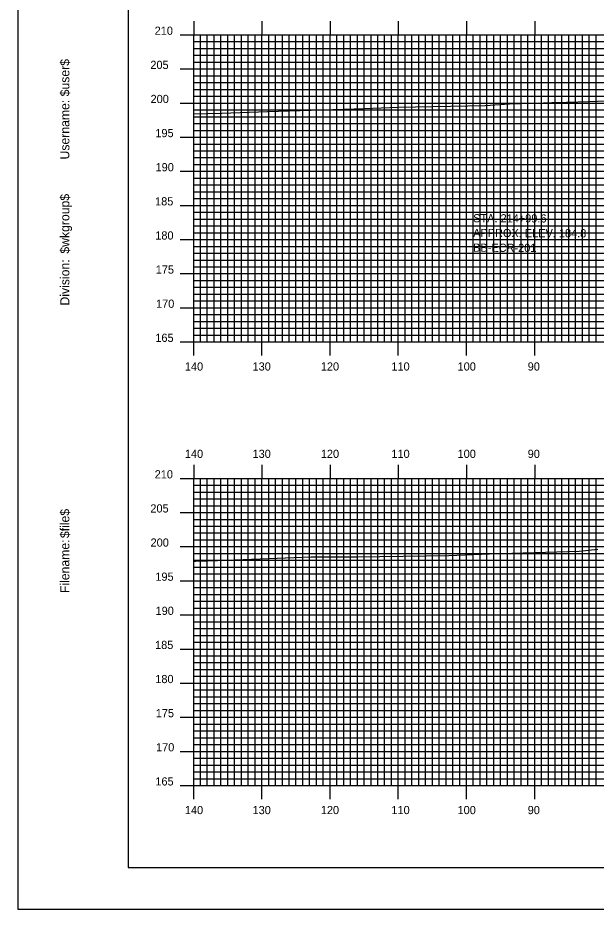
# Model space of a CAD drawing. Extents: x 1796027 to 1796370, y 442591 to 442811.
# Drawn here: x 1796026.6 to 1796111.4, y 442590.5 to 442721.2 of the extents above; entities that cross this region are included whole.
import ezdxf

# ---------------------------------------------------------------- set-up
doc = ezdxf.new("R2010")
doc.units = 0
for name, color, linetype in [('BORDER', 7, 'Continuous'), ('BORING - REFUSAL', 7, 'Continuous'), ('D_Roadway_Centerline', 7, 'Continuous'), ('H_V ANNOTATION', 7, 'Continuous'), ('MAJOR', 7, 'Continuous'), ('MINOR', 7, 'Continuous'), ('PLOT BOUNDARY', 7, 'Continuous'), ('S_Roadway_Centerline', 7, 'Continuous')]:
    doc.layers.add(name, color=color, linetype=linetype)

msp = doc.modelspace()

# ---------------------------------------------------------------- linework, layer by layer
at = {"layer": 'BORDER'}
msp.add_lwpolyline([(1796042.79, 442596.67), (1796362.79, 442596.67), (1796362.79, 442806.67), (1796042.79, 442806.67)], close=True, dxfattribs=at)
at = {"layer": 'D_Roadway_Centerline'}
msp.add_lwpolyline([(1796104.9, 442708.75), (1796105.52, 442708.73)], dxfattribs=at)
at = {"layer": 'MAJOR'}
for p, q in [((1796052.39, 442720.67), (1796052.39, 442718.67)), ((1796062.39, 442720.67), (1796062.39, 442718.67)), ((1796072.39, 442720.67), (1796072.39, 442718.67)), ((1796082.39, 442720.67), (1796082.39, 442718.67)), ((1796092.39, 442720.67), (1796092.39, 442718.67)), ((1796102.39, 442720.67), (1796102.39, 442718.67)), ((1796050.39, 442718.67), (1796052.39, 442718.67)), ((1796052.39, 442718.67), (1796332.39, 442718.67)), ((1796052.39, 442673.67), (1796052.39, 442718.67)), ((1796052.39, 442673.67), (1796052.39, 442718.67)), ((1796052.39, 442718.67), (1796332.39, 442718.67)), ((1796062.39, 442673.67), (1796062.39, 442718.67)), ((1796072.39, 442673.67), (1796072.39, 442718.67)), ((1796082.39, 442673.67), (1796082.39, 442718.67)), ((1796092.39, 442673.67), (1796092.39, 442718.67)), ((1796102.39, 442673.67), (1796102.39, 442718.67)), ((1796050.39, 442713.67), (1796052.39, 442713.67)), ((1796052.39, 442713.67), (1796332.39, 442713.67)), ((1796050.39, 442708.67), (1796052.39, 442708.67)), ((1796052.39, 442708.67), (1796332.39, 442708.67)), ((1796050.39, 442703.67), (1796052.39, 442703.67)), ((1796052.39, 442703.67), (1796332.39, 442703.67)), ((1796050.39, 442698.67), (1796052.39, 442698.67)), ((1796052.39, 442698.67), (1796332.39, 442698.67)), ((1796050.39, 442693.67), (1796052.39, 442693.67)), ((1796052.39, 442693.67), (1796332.39, 442693.67)), ((1796050.39, 442688.67), (1796052.39, 442688.67)), ((1796052.39, 442688.67), (1796332.39, 442688.67)), ((1796050.39, 442683.67), (1796052.39, 442683.67)), ((1796052.39, 442683.67), (1796332.39, 442683.67)), ((1796050.39, 442678.67), (1796052.39, 442678.67)), ((1796052.39, 442678.67), (1796332.39, 442678.67)), ((1796050.39, 442673.67), (1796052.39, 442673.67)), ((1796052.39, 442673.67), (1796332.39, 442673.67)), ((1796052.39, 442673.67), (1796332.39, 442673.67)), ((1796052.39, 442671.66), (1796052.39, 442673.67)), ((1796062.39, 442671.66), (1796062.39, 442673.67)), ((1796072.39, 442671.66), (1796072.39, 442673.67)), ((1796082.39, 442671.66), (1796082.39, 442673.67)), ((1796092.39, 442671.66), (1796092.39, 442673.67)), ((1796102.39, 442671.66), (1796102.39, 442673.67)), ((1796052.39, 442655.67), (1796052.39, 442653.67)), ((1796062.39, 442655.67), (1796062.39, 442653.67)), ((1796072.39, 442655.67), (1796072.39, 442653.67)), ((1796082.39, 442655.67), (1796082.39, 442653.67)), ((1796092.39, 442655.67), (1796092.39, 442653.67)), ((1796102.39, 442655.67), (1796102.39, 442653.67)), ((1796050.39, 442653.67), (1796052.39, 442653.67)), ((1796052.39, 442653.67), (1796332.39, 442653.67)), ((1796052.39, 442608.67), (1796052.39, 442653.67)), ((1796052.39, 442608.67), (1796052.39, 442653.67)), ((1796052.39, 442653.67), (1796332.39, 442653.67)), ((1796062.39, 442608.67), (1796062.39, 442653.67)), ((1796072.39, 442608.67), (1796072.39, 442653.67)), ((1796082.39, 442608.67), (1796082.39, 442653.67)), ((1796092.39, 442608.67), (1796092.39, 442653.67)), ((1796102.39, 442608.67), (1796102.39, 442653.67)), ((1796050.39, 442648.67), (1796052.39, 442648.67)), ((1796052.39, 442648.67), (1796332.39, 442648.67)), ((1796050.39, 442643.67), (1796052.39, 442643.67)), ((1796052.39, 442643.67), (1796332.39, 442643.67)), ((1796050.39, 442638.67), (1796052.39, 442638.67)), ((1796052.39, 442638.67), (1796332.39, 442638.67)), ((1796050.39, 442633.67), (1796052.39, 442633.67)), ((1796052.39, 442633.67), (1796332.39, 442633.67)), ((1796050.39, 442628.67), (1796052.39, 442628.67)), ((1796052.39, 442628.67), (1796332.39, 442628.67)), ((1796050.39, 442623.67), (1796052.39, 442623.67)), ((1796052.39, 442623.67), (1796332.39, 442623.67)), ((1796050.39, 442618.67), (1796052.39, 442618.67)), ((1796052.39, 442618.67), (1796332.39, 442618.67)), ((1796050.39, 442613.67), (1796052.39, 442613.67)), ((1796052.39, 442613.67), (1796332.39, 442613.67)), ((1796050.39, 442608.67), (1796052.39, 442608.67)), ((1796052.39, 442608.67), (1796332.39, 442608.67)), ((1796052.39, 442608.67), (1796332.39, 442608.67)), ((1796052.39, 442606.66), (1796052.39, 442608.67)), ((1796062.39, 442606.66), (1796062.39, 442608.67)), ((1796072.39, 442606.66), (1796072.39, 442608.67)), ((1796082.39, 442606.66), (1796082.39, 442608.67)), ((1796092.39, 442606.66), (1796092.39, 442608.67)), ((1796102.39, 442606.66), (1796102.39, 442608.67))]:
    msp.add_line(p, q, dxfattribs=at)
at = {"layer": 'MINOR'}
for p, q in [((1796053.39, 442673.67), (1796053.39, 442718.67)), ((1796054.39, 442673.67), (1796054.39, 442718.67)), ((1796055.39, 442673.67), (1796055.39, 442718.67)), ((1796056.39, 442673.67), (1796056.39, 442718.67)), ((1796057.39, 442673.67), (1796057.39, 442718.67)), ((1796058.39, 442673.67), (1796058.39, 442718.67)), ((1796059.39, 442673.67), (1796059.39, 442718.67)), ((1796060.39, 442673.67), (1796060.39, 442718.67)), ((1796061.39, 442673.67), (1796061.39, 442718.67)), ((1796063.39, 442673.67), (1796063.39, 442718.67)), ((1796064.39, 442673.67), (1796064.39, 442718.67)), ((1796065.39, 442673.67), (1796065.39, 442718.67)), ((1796066.39, 442673.67), (1796066.39, 442718.67)), ((1796067.39, 442673.67), (1796067.39, 442718.67)), ((1796068.39, 442673.67), (1796068.39, 442718.67)), ((1796069.39, 442673.67), (1796069.39, 442718.67)), ((1796070.39, 442673.67), (1796070.39, 442718.67)), ((1796071.39, 442673.67), (1796071.39, 442718.67)), ((1796073.39, 442673.67), (1796073.39, 442718.67)), ((1796074.39, 442673.67), (1796074.39, 442718.67)), ((1796075.39, 442673.67), (1796075.39, 442718.67)), ((1796076.39, 442673.67), (1796076.39, 442718.67)), ((1796077.39, 442673.67), (1796077.39, 442718.67)), ((1796078.39, 442673.67), (1796078.39, 442718.67)), ((1796079.39, 442673.67), (1796079.39, 442718.67)), ((1796080.39, 442673.67), (1796080.39, 442718.67)), ((1796081.39, 442673.67), (1796081.39, 442718.67)), ((1796083.39, 442673.67), (1796083.39, 442718.67)), ((1796084.39, 442673.67), (1796084.39, 442718.67)), ((1796085.39, 442673.67), (1796085.39, 442718.67)), ((1796086.39, 442673.67), (1796086.39, 442718.67)), ((1796087.39, 442673.67), (1796087.39, 442718.67)), ((1796088.39, 442673.67), (1796088.39, 442718.67)), ((1796089.39, 442673.67), (1796089.39, 442718.67)), ((1796090.39, 442673.67), (1796090.39, 442718.67)), ((1796091.39, 442673.67), (1796091.39, 442718.67)), ((1796093.39, 442673.67), (1796093.39, 442718.67)), ((1796094.39, 442673.67), (1796094.39, 442718.67)), ((1796095.39, 442673.67), (1796095.39, 442718.67)), ((1796096.39, 442673.67), (1796096.39, 442718.67)), ((1796097.39, 442673.67), (1796097.39, 442718.67)), ((1796098.39, 442673.67), (1796098.39, 442718.67)), ((1796099.39, 442673.67), (1796099.39, 442718.67)), ((1796100.39, 442673.67), (1796100.39, 442718.67)), ((1796101.39, 442673.67), (1796101.39, 442718.67)), ((1796103.39, 442673.67), (1796103.39, 442718.67)), ((1796104.39, 442673.67), (1796104.39, 442718.67)), ((1796105.39, 442673.67), (1796105.39, 442718.67)), ((1796106.39, 442673.67), (1796106.39, 442718.67)), ((1796107.39, 442673.67), (1796107.39, 442718.67)), ((1796108.39, 442673.67), (1796108.39, 442718.67)), ((1796109.39, 442673.67), (1796109.39, 442718.67)), ((1796110.39, 442673.67), (1796110.39, 442718.67)), ((1796111.39, 442673.67), (1796111.39, 442718.67)), ((1796052.39, 442717.67), (1796332.39, 442717.67)), ((1796052.39, 442717.67), (1796054.4, 442717.67)), ((1796052.39, 442716.67), (1796332.39, 442716.67)), ((1796052.39, 442716.67), (1796054.4, 442716.67)), ((1796052.39, 442715.67), (1796332.39, 442715.67)), ((1796052.39, 442715.67), (1796054.4, 442715.67)), ((1796052.39, 442714.67), (1796332.39, 442714.67)), ((1796052.39, 442714.67), (1796054.4, 442714.67)), ((1796052.39, 442712.67), (1796332.39, 442712.67)), ((1796052.39, 442712.67), (1796054.4, 442712.67)), ((1796052.39, 442711.67), (1796332.39, 442711.67)), ((1796052.39, 442711.67), (1796054.4, 442711.67)), ((1796052.39, 442710.67), (1796332.39, 442710.67)), ((1796052.39, 442710.67), (1796054.4, 442710.67)), ((1796052.39, 442709.67), (1796332.39, 442709.67)), ((1796052.39, 442709.67), (1796054.4, 442709.67)), ((1796052.39, 442707.67), (1796332.39, 442707.67)), ((1796052.39, 442707.67), (1796054.4, 442707.67)), ((1796052.39, 442706.67), (1796332.39, 442706.67)), ((1796052.39, 442706.67), (1796054.4, 442706.67)), ((1796052.39, 442705.67), (1796332.39, 442705.67)), ((1796052.39, 442705.67), (1796054.4, 442705.67)), ((1796052.39, 442704.67), (1796332.39, 442704.67)), ((1796052.39, 442704.67), (1796054.4, 442704.67)), ((1796052.39, 442702.67), (1796332.39, 442702.67)), ((1796052.39, 442702.67), (1796054.4, 442702.67)), ((1796052.39, 442701.67), (1796332.39, 442701.67)), ((1796052.39, 442701.67), (1796054.4, 442701.67)), ((1796052.39, 442700.67), (1796332.39, 442700.67)), ((1796052.39, 442700.67), (1796054.4, 442700.67)), ((1796052.39, 442699.67), (1796332.39, 442699.67)), ((1796052.39, 442699.67), (1796054.4, 442699.67)), ((1796052.39, 442697.67), (1796332.39, 442697.67)), ((1796052.39, 442697.67), (1796054.4, 442697.67)), ((1796052.39, 442696.67), (1796332.39, 442696.67)), ((1796052.39, 442696.67), (1796054.4, 442696.67)), ((1796052.39, 442695.67), (1796332.39, 442695.67)), ((1796052.39, 442695.67), (1796054.4, 442695.67)), ((1796052.39, 442694.67), (1796332.39, 442694.67)), ((1796052.39, 442694.67), (1796054.4, 442694.67)), ((1796052.39, 442692.67), (1796332.39, 442692.67)), ((1796052.39, 442692.67), (1796054.4, 442692.67)), ((1796052.39, 442691.67), (1796332.39, 442691.67)), ((1796052.39, 442691.67), (1796054.4, 442691.67)), ((1796052.39, 442690.67), (1796332.39, 442690.67)), ((1796052.39, 442690.67), (1796054.4, 442690.67)), ((1796052.39, 442689.67), (1796332.39, 442689.67)), ((1796052.39, 442689.67), (1796054.4, 442689.67)), ((1796052.39, 442687.67), (1796332.39, 442687.67)), ((1796052.39, 442687.67), (1796054.4, 442687.67)), ((1796052.39, 442686.67), (1796332.39, 442686.67)), ((1796052.39, 442686.67), (1796054.4, 442686.67)), ((1796052.39, 442685.67), (1796332.39, 442685.67)), ((1796052.39, 442685.67), (1796054.4, 442685.67)), ((1796052.39, 442684.67), (1796332.39, 442684.67)), ((1796052.39, 442684.67), (1796054.4, 442684.67)), ((1796052.39, 442682.67), (1796332.39, 442682.67)), ((1796052.39, 442682.67), (1796054.4, 442682.67)), ((1796052.39, 442681.67), (1796332.39, 442681.67)), ((1796052.39, 442681.67), (1796054.4, 442681.67)), ((1796052.39, 442680.67), (1796332.39, 442680.67)), ((1796052.39, 442680.67), (1796054.4, 442680.67)), ((1796052.39, 442679.67), (1796332.39, 442679.67)), ((1796052.39, 442679.67), (1796054.4, 442679.67)), ((1796052.39, 442677.67), (1796332.39, 442677.67)), ((1796052.39, 442677.67), (1796054.4, 442677.67)), ((1796052.39, 442676.67), (1796332.39, 442676.67)), ((1796052.39, 442676.67), (1796054.4, 442676.67)), ((1796052.39, 442675.67), (1796332.39, 442675.67)), ((1796052.39, 442675.67), (1796054.4, 442675.67)), ((1796052.39, 442674.67), (1796332.39, 442674.67)), ((1796052.39, 442674.67), (1796054.4, 442674.67)), ((1796052.39, 442652.67), (1796332.39, 442652.67)), ((1796052.39, 442652.67), (1796054.4, 442652.67)), ((1796053.39, 442608.67), (1796053.39, 442653.67)), ((1796054.39, 442608.67), (1796054.39, 442653.67)), ((1796055.39, 442608.67), (1796055.39, 442653.67)), ((1796056.39, 442608.67), (1796056.39, 442653.67)), ((1796057.39, 442608.67), (1796057.39, 442653.67)), ((1796058.39, 442608.67), (1796058.39, 442653.67)), ((1796059.39, 442608.67), (1796059.39, 442653.67)), ((1796060.39, 442608.67), (1796060.39, 442653.67)), ((1796061.39, 442608.67), (1796061.39, 442653.67)), ((1796063.39, 442608.67), (1796063.39, 442653.67)), ((1796064.39, 442608.67), (1796064.39, 442653.67)), ((1796065.39, 442608.67), (1796065.39, 442653.67)), ((1796066.39, 442608.67), (1796066.39, 442653.67)), ((1796067.39, 442608.67), (1796067.39, 442653.67)), ((1796068.39, 442608.67), (1796068.39, 442653.67)), ((1796069.39, 442608.67), (1796069.39, 442653.67)), ((1796070.39, 442608.67), (1796070.39, 442653.67)), ((1796071.39, 442608.67), (1796071.39, 442653.67)), ((1796073.39, 442608.67), (1796073.39, 442653.67)), ((1796074.39, 442608.67), (1796074.39, 442653.67)), ((1796075.39, 442608.67), (1796075.39, 442653.67)), ((1796076.39, 442608.67), (1796076.39, 442653.67)), ((1796077.39, 442608.67), (1796077.39, 442653.67)), ((1796078.39, 442608.67), (1796078.39, 442653.67)), ((1796079.39, 442608.67), (1796079.39, 442653.67)), ((1796080.39, 442608.67), (1796080.39, 442653.67)), ((1796081.39, 442608.67), (1796081.39, 442653.67)), ((1796083.39, 442608.67), (1796083.39, 442653.67)), ((1796084.39, 442608.67), (1796084.39, 442653.67)), ((1796085.39, 442608.67), (1796085.39, 442653.67)), ((1796086.39, 442608.67), (1796086.39, 442653.67)), ((1796087.39, 442608.67), (1796087.39, 442653.67)), ((1796088.39, 442608.67), (1796088.39, 442653.67)), ((1796089.39, 442608.67), (1796089.39, 442653.67)), ((1796090.39, 442608.67), (1796090.39, 442653.67)), ((1796091.39, 442608.67), (1796091.39, 442653.67)), ((1796093.39, 442608.67), (1796093.39, 442653.67)), ((1796094.39, 442608.67), (1796094.39, 442653.67)), ((1796095.39, 442608.67), (1796095.39, 442653.67)), ((1796096.39, 442608.67), (1796096.39, 442653.67)), ((1796097.39, 442608.67), (1796097.39, 442653.67)), ((1796098.39, 442608.67), (1796098.39, 442653.67)), ((1796099.39, 442608.67), (1796099.39, 442653.67)), ((1796100.39, 442608.67), (1796100.39, 442653.67)), ((1796101.39, 442608.67), (1796101.39, 442653.67)), ((1796103.39, 442608.67), (1796103.39, 442653.67)), ((1796104.39, 442608.67), (1796104.39, 442653.67)), ((1796105.39, 442608.67), (1796105.39, 442653.67)), ((1796106.39, 442608.67), (1796106.39, 442653.67)), ((1796107.39, 442608.67), (1796107.39, 442653.67)), ((1796108.39, 442608.67), (1796108.39, 442653.67)), ((1796109.39, 442608.67), (1796109.39, 442653.67)), ((1796110.39, 442608.67), (1796110.39, 442653.67)), ((1796111.39, 442608.67), (1796111.39, 442653.67)), ((1796052.39, 442651.67), (1796332.39, 442651.67)), ((1796052.39, 442651.67), (1796054.4, 442651.67)), ((1796052.39, 442650.67), (1796332.39, 442650.67)), ((1796052.39, 442650.67), (1796054.4, 442650.67)), ((1796052.39, 442649.67), (1796332.39, 442649.67)), ((1796052.39, 442649.67), (1796054.4, 442649.67)), ((1796052.39, 442647.67), (1796332.39, 442647.67)), ((1796052.39, 442647.67), (1796054.4, 442647.67)), ((1796052.39, 442646.67), (1796332.39, 442646.67)), ((1796052.39, 442646.67), (1796054.4, 442646.67)), ((1796052.39, 442645.67), (1796332.39, 442645.67)), ((1796052.39, 442645.67), (1796054.4, 442645.67)), ((1796052.39, 442644.67), (1796332.39, 442644.67)), ((1796052.39, 442644.67), (1796054.4, 442644.67)), ((1796052.39, 442642.67), (1796332.39, 442642.67)), ((1796052.39, 442642.67), (1796054.4, 442642.67)), ((1796052.39, 442641.67), (1796332.39, 442641.67)), ((1796052.39, 442641.67), (1796054.4, 442641.67)), ((1796052.39, 442640.67), (1796332.39, 442640.67)), ((1796052.39, 442640.67), (1796054.4, 442640.67)), ((1796052.39, 442639.67), (1796332.39, 442639.67)), ((1796052.39, 442639.67), (1796054.4, 442639.67)), ((1796052.39, 442637.67), (1796332.39, 442637.67)), ((1796052.39, 442637.67), (1796054.4, 442637.67)), ((1796052.39, 442636.67), (1796332.39, 442636.67)), ((1796052.39, 442636.67), (1796054.4, 442636.67)), ((1796052.39, 442635.67), (1796332.39, 442635.67)), ((1796052.39, 442635.67), (1796054.4, 442635.67)), ((1796052.39, 442634.67), (1796332.39, 442634.67)), ((1796052.39, 442634.67), (1796054.4, 442634.67)), ((1796052.39, 442632.67), (1796332.39, 442632.67)), ((1796052.39, 442632.67), (1796054.4, 442632.67)), ((1796052.39, 442631.67), (1796332.39, 442631.67)), ((1796052.39, 442631.67), (1796054.4, 442631.67)), ((1796052.39, 442630.67), (1796332.39, 442630.67)), ((1796052.39, 442630.67), (1796054.4, 442630.67)), ((1796052.39, 442629.67), (1796332.39, 442629.67)), ((1796052.39, 442629.67), (1796054.4, 442629.67)), ((1796052.39, 442627.67), (1796332.39, 442627.67)), ((1796052.39, 442627.67), (1796054.4, 442627.67)), ((1796052.39, 442626.67), (1796332.39, 442626.67)), ((1796052.39, 442626.67), (1796054.4, 442626.67)), ((1796052.39, 442625.67), (1796332.39, 442625.67)), ((1796052.39, 442625.67), (1796054.4, 442625.67)), ((1796052.39, 442624.67), (1796332.39, 442624.67)), ((1796052.39, 442624.67), (1796054.4, 442624.67)), ((1796052.39, 442622.67), (1796332.39, 442622.67)), ((1796052.39, 442622.67), (1796054.4, 442622.67)), ((1796052.39, 442621.67), (1796332.39, 442621.67)), ((1796052.39, 442621.67), (1796054.4, 442621.67)), ((1796052.39, 442620.67), (1796332.39, 442620.67)), ((1796052.39, 442620.67), (1796054.4, 442620.67)), ((1796052.39, 442619.67), (1796332.39, 442619.67)), ((1796052.39, 442619.67), (1796054.4, 442619.67)), ((1796052.39, 442617.67), (1796332.39, 442617.67)), ((1796052.39, 442617.67), (1796054.4, 442617.67)), ((1796052.39, 442616.67), (1796332.39, 442616.67)), ((1796052.39, 442616.67), (1796054.4, 442616.67)), ((1796052.39, 442615.67), (1796332.39, 442615.67)), ((1796052.39, 442615.67), (1796054.4, 442615.67)), ((1796052.39, 442614.67), (1796332.39, 442614.67)), ((1796052.39, 442614.67), (1796054.4, 442614.67)), ((1796052.39, 442612.67), (1796332.39, 442612.67)), ((1796052.39, 442612.67), (1796054.4, 442612.67)), ((1796052.39, 442611.67), (1796332.39, 442611.67)), ((1796052.39, 442611.67), (1796054.4, 442611.67)), ((1796052.39, 442610.67), (1796332.39, 442610.67)), ((1796052.39, 442610.67), (1796054.4, 442610.67)), ((1796052.39, 442609.67), (1796332.39, 442609.67)), ((1796052.39, 442609.67), (1796054.4, 442609.67))]:
    msp.add_line(p, q, dxfattribs=at)
at = {"layer": 'PLOT BOUNDARY'}
msp.add_lwpolyline([(1796026.61, 442590.55), (1796366.61, 442590.55), (1796366.61, 442810.55), (1796026.61, 442810.55)], close=True, dxfattribs=at)
at = {"layer": 'S_Roadway_Centerline'}
for points in [[(1796052.39, 442707.09), (1796056.51, 442707.21), (1796063.22, 442707.41), (1796074.39, 442707.79), (1796077.39, 442707.88), (1796082.39, 442708.05), (1796095.11, 442708.32), (1796098.67, 442708.55), (1796103.66, 442708.72), (1796110.44, 442708.89), (1796115.06, 442709.09)], [(1796052.39, 442641.5), (1796052.67, 442641.52), (1796055.88, 442641.65), (1796069.61, 442642.18), (1796076.25, 442642.2), (1796086.5, 442642.32), (1796089.8, 442642.38), (1796095.77, 442642.64), (1796108.9, 442643.03), (1796111.65, 442643.31)]]:
    msp.add_lwpolyline(points, dxfattribs=at)

# ---------------------------------------------------------------- texts
at = {"layer": 'BORDER'}
for s, p in [('$user$', (1796034.16, 442709.65)), ('Username:', (1796034.16, 442700.4)), ('$wkgroup$', (1796034.16, 442686.6)), ('Division:', (1796034.16, 442679)), ('$file$', (1796034.16, 442644.92)), ('Filename:', (1796034.16, 442636.86))]:
    msp.add_text(s, height=1.339, rotation=90, dxfattribs=at).set_placement(p)
at = {"layer": 'BORING - REFUSAL'}
for s, p in [('STA. 214+99.6', (1796093.37, 442691.2)), ('APPROX. ELEV. 184.8', (1796093.36, 442689.04)), ('BB-ECR-201', (1796093.36, 442686.88))]:
    msp.add_text(s, height=1.2, rotation=359.8142, dxfattribs=at).set_placement(p)
at = {"layer": 'H_V ANNOTATION'}
for s, p in [('210', (1796046.67, 442718.67)), ('205', (1796046.04, 442713.67)), ('200', (1796046.07, 442708.67)), ('195', (1796046.77, 442703.67)), ('190', (1796046.8, 442698.67)), ('185', (1796046.73, 442693.67)), ('180', (1796046.76, 442688.67)), ('175', (1796046.83, 442683.67)), ('170', (1796046.87, 442678.67)), ('165', (1796046.77, 442673.67)), ('140', (1796051.1, 442669.47)), ('130', (1796061.02, 442669.47)), ('120', (1796071.03, 442669.47)), ('110', (1796081.38, 442669.47)), ('100', (1796091.08, 442669.47)), ('90', (1796101.36, 442669.47)), ('140', (1796051.1, 442656.67)), ('130', (1796061.02, 442656.67)), ('120', (1796071.03, 442656.67)), ('110', (1796081.38, 442656.67)), ('100', (1796091.08, 442656.67)), ('90', (1796101.36, 442656.67)), ('210', (1796046.67, 442653.67)), ('205', (1796046.04, 442648.67)), ('200', (1796046.07, 442643.67)), ('195', (1796046.77, 442638.67)), ('190', (1796046.8, 442633.67)), ('185', (1796046.73, 442628.67)), ('180', (1796046.76, 442623.67)), ('175', (1796046.83, 442618.67)), ('170', (1796046.87, 442613.67)), ('165', (1796046.77, 442608.67)), ('140', (1796051.1, 442604.47)), ('130', (1796061.02, 442604.47)), ('120', (1796071.03, 442604.47)), ('110', (1796081.38, 442604.47)), ('100', (1796091.08, 442604.47)), ('90', (1796101.36, 442604.47))]:
    msp.add_text(s, height=1.2, dxfattribs=at).set_placement(p)
at = {"layer": 'MAJOR'}
for p in [(1796052.38, 442673.67), (1796052.38, 442608.67)]:
    msp.add_text('-', height=0.012, dxfattribs=at).set_placement(p)

doc.saveas('drawing.dxf')
